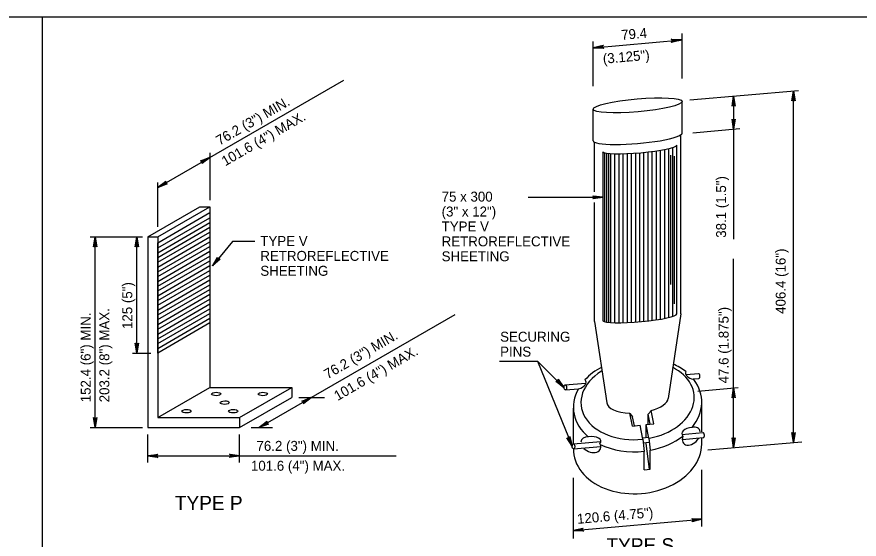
# Model space of a CAD drawing. Extents: x 640253 to 641999, y 298458 to 299646.
# Drawn here: x 640544.6 to 640798.8, y 298630.1 to 298787.7 of the extents above; entities that cross this region are included whole.
import ezdxf

# ---------------------------------------------------------------- set-up
doc = ezdxf.new("R2010")
doc.units = 0
doc.layers.add('1', color=7, linetype='Continuous')
doc.layers.add('2', color=7, linetype='Continuous')

msp = doc.modelspace()

# ---------------------------------------------------------------- linework, layer by layer
at = {"layer": '1'}
for p, q in [((640293.31, 298787.67), (641079.31, 298787.67)), ((640552.4, 298501.97), (640552.4, 298787.67))]:
    msp.add_line(p, q, dxfattribs=at)
at = {"layer": '2'}
for p, q in [((640745.35, 298769.11), (640745.35, 298782.64)), ((640718.51, 298778.37), (640745.35, 298780.72)), ((640718.51, 298766.76), (640718.51, 298780.28)), ((640587.19, 298736.22), (640643.29, 298768.61)), ((640747.71, 298762.61), (640780.48, 298765.48)), ((640760.93, 298763.77), (640760.93, 298753.8)), ((640778.98, 298659.27), (640778.98, 298765.33)), ((640745.35, 298752.61), (640745.35, 298762.15)), ((640718.51, 298750.3), (640718.51, 298759.84)), ((640748.58, 298752.71), (640762.8, 298753.96)), ((640760.93, 298753.8), (640760.93, 298720.65)), ((640744.97, 298698.11), (640744.96, 298752.08)), ((640718.9, 298734.89), (640718.9, 298749.84)), ((640742.61, 298697.33), (640742.61, 298748.3)), ((640743.76, 298748.51), (640743.55, 298748.73)), ((640743.77, 298698.07), (640743.76, 298748.98)), ((640602.93, 298732.38), (640602.93, 298746.61)), ((640721.41, 298746.98), (640721.41, 298696)), ((640721.41, 298746.59), (640721.63, 298746.81)), ((640722.06, 298695.59), (640722.06, 298746.56)), ((640722.61, 298695.59), (640722.61, 298746.55)), ((640723.24, 298695.59), (640723.24, 298746.56)), ((640723.86, 298695.45), (640723.86, 298746.43)), ((640725.11, 298695.4), (640725.11, 298746.37)), ((640726.36, 298695.39), (640726.36, 298746.36)), ((640727.61, 298695.4), (640727.61, 298746.38)), ((640728.86, 298695.45), (640728.86, 298746.42)), ((640730.11, 298695.51), (640730.11, 298746.48)), ((640731.36, 298695.59), (640731.36, 298746.57)), ((640732.61, 298695.69), (640732.61, 298746.66)), ((640733.86, 298695.81), (640733.86, 298746.78)), ((640735.11, 298695.94), (640735.11, 298746.91)), ((640736.36, 298696.1), (640736.36, 298747.07)), ((640737.61, 298696.27), (640737.61, 298747.24)), ((640738.86, 298696.47), (640738.86, 298747.44)), ((640740.11, 298696.7), (640740.11, 298747.67)), ((640741.36, 298696.98), (640741.36, 298747.95)), ((640741.93, 298706.99), (640741.93, 298745.92)), ((640743.12, 298701.13), (640743.12, 298745.69)), ((640587.19, 298724.38), (640587.19, 298737.68)), ((640698.95, 298733.24), (640721.41, 298733.24)), ((640584.12, 298721.28), (640599.86, 298730.37)), ((640587.12, 298721.28), (640602.86, 298730.37)), ((640599.86, 298730.37), (640602.86, 298730.37)), ((640602.86, 298730.37), (640602.86, 298675.87)), ((640718.91, 298695.83), (640718.9, 298731.67)), ((640587.12, 298717.99), (640602.86, 298727.08)), ((640587.12, 298716.54), (640602.86, 298725.63)), ((640587.12, 298715.1), (640602.86, 298724.19)), ((640587.12, 298713.66), (640602.86, 298722.75)), ((640566.74, 298721.28), (640582.49, 298721.28)), ((640568.28, 298663.78), (640568.28, 298721.28)), ((640580.82, 298686.28), (640580.82, 298721.28)), ((640584.12, 298721.28), (640587.12, 298721.28)), ((640584.12, 298721.28), (640584.12, 298663.78)), ((640587.12, 298712.21), (640602.86, 298721.3)), ((640587.12, 298721.28), (640587.12, 298666.78)), ((640587.12, 298710.77), (640602.86, 298719.86)), ((640587.12, 298719.28), (640587.35, 298719.68)), ((640587.12, 298719.32), (640587.32, 298719.66)), ((640587.12, 298709.33), (640602.86, 298718.41)), ((640609.71, 298719.96), (640603.7, 298712.54)), ((640616.48, 298719.96), (640609.71, 298719.96)), ((640587.12, 298707.88), (640602.86, 298716.97)), ((640587.12, 298706.44), (640602.86, 298715.53)), ((640587.12, 298705), (640602.86, 298714.09)), ((640587.12, 298703.55), (640602.86, 298712.64)), ((640760.93, 298657.71), (640760.93, 298714.7)), ((640587.12, 298702.11), (640602.86, 298711.2)), ((640587.12, 298700.67), (640602.86, 298709.75)), ((640587.12, 298699.22), (640602.86, 298708.31)), ((640587.12, 298697.78), (640602.86, 298706.87)), ((640587.12, 298696.34), (640602.86, 298705.43)), ((640587.12, 298694.89), (640602.86, 298703.98)), ((640587.12, 298693.45), (640602.86, 298702.54)), ((640587.12, 298692.01), (640602.86, 298701.09)), ((640587.12, 298690.56), (640602.86, 298699.65)), ((640587.12, 298689.12), (640602.86, 298698.21)), ((640617.72, 298663.78), (640676.89, 298697.94)), ((640744.97, 298698.11), (640741.18, 298672.58)), ((640587.12, 298687.68), (640602.86, 298696.76)), ((640718.91, 298695.83), (640722.69, 298671.24)), ((640579.47, 298686.28), (640585.04, 298686.28)), ((640690.3, 298683.85), (640701.76, 298683.85)), ((640701.76, 298683.85), (640709.73, 298675.91)), ((640701.76, 298683.85), (640712.18, 298658.13)), ((640746.61, 298679.77), (640750.3, 298680.09)), ((640710.07, 298676.65), (640716.25, 298677.17)), ((640748.75, 298678.44), (640750.42, 298678.58)), ((640587.12, 298666.78), (640602.86, 298675.87)), ((640602.86, 298675.87), (640627.58, 298675.87)), ((640611.84, 298666.78), (640627.58, 298675.87)), ((640627.58, 298675.87), (640627.58, 298672.87)), ((640710.18, 298675.14), (640714.07, 298675.47)), ((640750.09, 298674.81), (640762.33, 298675.88)), ((640611.84, 298663.78), (640627.58, 298672.87)), ((640629.69, 298672.87), (640637.47, 298672.87)), ((640712.57, 298658.9), (640712.57, 298669.6)), ((640751.32, 298662.52), (640751.32, 298671.49)), ((640587.12, 298666.78), (640611.84, 298666.78)), ((640611.84, 298666.78), (640611.84, 298663.78)), ((640730.36, 298664.26), (640729.56, 298668.13)), ((640729.58, 298668.02), (640730.45, 298667.02)), ((640731.01, 298664.3), (640730.45, 298667.02)), ((640736.01, 298668.88), (640735.1, 298667.79)), ((640735.1, 298664.75), (640735.1, 298667.79)), ((640735.72, 298664.82), (640735.1, 298667.79)), ((640736.83, 298664.91), (640736, 298668.9)), ((640730.36, 298664.26), (640732.68, 298664.47)), ((640733.56, 298660.25), (640732.68, 298664.47)), ((640734.51, 298664.7), (640736.83, 298664.91)), ((640735.37, 298660.56), (640734.51, 298664.7)), ((640734.51, 298660.92), (640734.51, 298664.7)), ((640566.74, 298663.78), (640582.49, 298663.78)), ((640584.12, 298663.78), (640611.84, 298663.78)), ((640584.12, 298653.23), (640584.12, 298661.74)), ((640611.84, 298653.23), (640611.84, 298661.74)), ((640615.31, 298663.78), (640621.72, 298663.78)), ((640745.28, 298661.72), (640751.64, 298662.26)), ((640712.51, 298658.91), (640720.85, 298659.63)), ((640733.46, 298660.71), (640735.31, 298660.86)), ((640733.56, 298660.25), (640733.88, 298656.62)), ((640733.65, 298659.21), (640735.48, 298659.36)), ((640735.5, 298651.22), (640734.51, 298659.03)), ((640735.37, 298660.56), (640735.7, 298656.93)), ((640745.44, 298660.21), (640751.77, 298660.75)), ((640751.32, 298658.55), (640751.32, 298660.75)), ((640753.15, 298657.03), (640781.49, 298659.51)), ((640712.63, 298657.41), (640720.84, 298658.11)), ((640733.88, 298651.05), (640733.88, 298656.62)), ((640735.7, 298651.21), (640735.7, 298656.93)), ((640584.12, 298655.27), (640659.11, 298655.27)), ((640733.88, 298651.05), (640735.7, 298651.21)), ((640751.32, 298633.93), (640751.32, 298651.02)), ((640712.57, 298630.28), (640712.57, 298648.65)), ((640712.57, 298632.73), (640751.32, 298636.12))]:
    msp.add_line(p, q, dxfattribs=at)
for points in [[(640721.62, 298778.25), (640721.48, 298778.47), (640718.51, 298778.37), (640721.62, 298778.25), (640721.78, 298778.13), (640718.51, 298778.37), (640721.45, 298778.78), (640721.54, 298779.01), (640718.51, 298778.37), (640721.69, 298779.17), (640721.54, 298779.01)], [(640721.62, 298778.25), (640721.48, 298778.47), (640718.51, 298778.37), (640721.62, 298778.25), (640721.78, 298778.13), (640718.51, 298778.37), (640721.45, 298778.78), (640721.54, 298779.01), (640718.51, 298778.37), (640721.69, 298779.17), (640721.54, 298779.01)], [(640742.24, 298780.84), (640742.38, 298780.63), (640745.35, 298780.72), (640742.24, 298780.84), (640742.07, 298780.96), (640745.35, 298780.72), (640742.41, 298780.32), (640742.32, 298780.09), (640745.35, 298780.72), (640742.17, 298779.92), (640742.32, 298780.09)], [(640760.57, 298760.91), (640760.78, 298761.02), (640760.93, 298763.77), (640760.57, 298760.91), (640760.45, 298760.77), (640760.93, 298763.77), (640761.06, 298761.02), (640761.27, 298760.92), (640760.93, 298763.77), (640761.41, 298760.77), (640761.27, 298760.92)], [(640778.62, 298762.47), (640778.83, 298762.58), (640778.98, 298765.33), (640778.62, 298762.47), (640778.5, 298762.33), (640778.98, 298765.33), (640779.12, 298762.58), (640779.32, 298762.48), (640778.98, 298765.33), (640779.46, 298762.33), (640779.32, 298762.48)], [(640761.29, 298756.65), (640761.08, 298756.54), (640760.93, 298753.8), (640761.29, 298756.65), (640761.41, 298756.8), (640760.93, 298753.8), (640760.79, 298756.54), (640760.59, 298756.64), (640760.93, 298753.8), (640760.45, 298756.8), (640760.59, 298756.64)], [(640600.28, 298744.19), (640600.48, 298744.07), (640602.93, 298745.31), (640600.28, 298744.19), (640600.09, 298744.23), (640602.93, 298745.31), (640600.62, 298743.82), (640600.64, 298743.59), (640602.93, 298745.31), (640600.57, 298743.39), (640600.64, 298743.59)], [(640589.84, 298737.33), (640589.64, 298737.46), (640587.19, 298736.22), (640589.84, 298737.33), (640590.03, 298737.3), (640587.19, 298736.22), (640589.5, 298737.71), (640589.48, 298737.93), (640587.19, 298736.22), (640589.55, 298738.13), (640589.48, 298737.93)], [(640718.56, 298733.6), (640718.66, 298733.39), (640721.41, 298733.24), (640718.56, 298733.6), (640718.41, 298733.72), (640721.41, 298733.24), (640718.66, 298733.11), (640718.56, 298732.9), (640721.41, 298733.24), (640718.41, 298732.76), (640718.56, 298732.9)], [(640567.92, 298718.43), (640568.13, 298718.53), (640568.28, 298721.28), (640567.92, 298718.43), (640567.8, 298718.28), (640568.28, 298721.28), (640568.42, 298718.53), (640568.62, 298718.43), (640568.28, 298721.28), (640568.76, 298718.28), (640568.62, 298718.43)], [(640580.46, 298718.43), (640580.67, 298718.53), (640580.82, 298721.28), (640580.46, 298718.43), (640580.34, 298718.28), (640580.82, 298721.28), (640580.96, 298718.53), (640581.16, 298718.43), (640580.82, 298721.28), (640581.3, 298718.28), (640581.16, 298718.43)], [(640605.78, 298714.53), (640605.55, 298714.58), (640603.7, 298712.54), (640605.78, 298714.53), (640605.97, 298714.56), (640603.7, 298712.54), (640605.33, 298714.75), (640605.23, 298714.96), (640603.7, 298712.54), (640605.22, 298715.17), (640605.23, 298714.96)], [(640581.18, 298689.13), (640580.97, 298689.03), (640580.82, 298686.28), (640581.18, 298689.13), (640581.3, 298689.28), (640580.82, 298686.28), (640580.69, 298689.03), (640580.48, 298689.13), (640580.82, 298686.28), (640580.34, 298689.28), (640580.48, 298689.13)], [(640707.95, 298678.17), (640707.88, 298677.95), (640709.73, 298675.91), (640707.95, 298678.17), (640707.93, 298678.36), (640709.73, 298675.91), (640707.68, 298677.74), (640707.47, 298677.67), (640709.73, 298675.91), (640707.26, 298677.68), (640707.47, 298677.67)], [(640760.57, 298672.9), (640760.78, 298673.01), (640760.93, 298675.75), (640760.57, 298672.9), (640760.45, 298672.75), (640760.93, 298675.75), (640761.06, 298673.01), (640761.27, 298672.91), (640760.93, 298675.75), (640761.41, 298672.75), (640761.27, 298672.91)], [(640630.82, 298671.76), (640631.02, 298671.63), (640633.47, 298672.87), (640630.82, 298671.76), (640630.63, 298671.79), (640633.47, 298672.87), (640631.16, 298671.38), (640631.18, 298671.16), (640633.47, 298672.87), (640631.11, 298670.96), (640631.18, 298671.16)], [(640568.64, 298666.63), (640568.43, 298666.53), (640568.28, 298663.78), (640568.64, 298666.63), (640568.76, 298666.78), (640568.28, 298663.78), (640568.14, 298666.53), (640567.94, 298666.63), (640568.28, 298663.78), (640567.8, 298666.78), (640567.94, 298666.63)], [(640620.37, 298664.9), (640620.18, 298665.02), (640617.72, 298663.78), (640620.37, 298664.9), (640620.56, 298664.86), (640617.72, 298663.78), (640620.03, 298665.27), (640620.02, 298665.5), (640617.72, 298663.78), (640620.08, 298665.69), (640620.02, 298665.5)], [(640779.34, 298662.13), (640779.13, 298662.02), (640778.98, 298659.27), (640779.34, 298662.13), (640779.46, 298662.27), (640778.98, 298659.27), (640778.85, 298662.02), (640778.64, 298662.12), (640778.98, 298659.27), (640778.5, 298662.27), (640778.64, 298662.12)], [(640711.42, 298660.91), (640711.27, 298660.73), (640712.18, 298658.13), (640711.42, 298660.91), (640711.48, 298661.09), (640712.18, 298658.13), (640711.01, 298660.62), (640710.78, 298660.64), (640712.18, 298658.13), (640710.59, 298660.73), (640710.78, 298660.64)], [(640761.29, 298660.57), (640761.08, 298660.46), (640760.93, 298657.71), (640761.29, 298660.57), (640761.41, 298660.71), (640760.93, 298657.71), (640760.79, 298660.46), (640760.59, 298660.56), (640760.93, 298657.71), (640760.45, 298660.71), (640760.59, 298660.56)], [(640586.97, 298654.91), (640586.87, 298655.12), (640584.12, 298655.27), (640586.97, 298654.91), (640587.12, 298654.79), (640584.12, 298655.27), (640586.87, 298655.41), (640586.97, 298655.61), (640584.12, 298655.27), (640587.12, 298655.75), (640586.97, 298655.61)], [(640608.98, 298655.63), (640609.09, 298655.42), (640611.84, 298655.27), (640608.98, 298655.63), (640608.84, 298655.75), (640611.84, 298655.27), (640609.09, 298655.14), (640608.99, 298654.93), (640611.84, 298655.27), (640608.84, 298654.79), (640608.99, 298654.93)], [(640748.44, 298636.23), (640748.57, 298636.03), (640751.32, 298636.12), (640748.44, 298636.23), (640748.29, 298636.34), (640751.32, 298636.12), (640748.6, 298635.75), (640748.51, 298635.53), (640751.32, 298636.12), (640748.37, 298635.38), (640748.51, 298635.53)], [(640715.45, 298632.62), (640715.32, 298632.82), (640712.57, 298632.73), (640715.45, 298632.62), (640715.6, 298632.51), (640712.57, 298632.73), (640715.29, 298633.1), (640715.37, 298633.32), (640712.57, 298632.73), (640715.52, 298633.47), (640715.37, 298633.32)]]:
    msp.add_lwpolyline(points, dxfattribs=at)
msp.add_lwpolyline([(640587.12, 298686.28), (640587.12, 298719.55), (640602.86, 298728.64), (640602.86, 298695.37)], close=True, dxfattribs=at)
for centre, major_axis, ratio in [((640731.93, 298760.98), (13.42, 1.17), 0.145281), ((640604.79, 298673.91), (1.39, 0.03), 0.379302), ((640618.87, 298673.91), (1.39, 0.03), 0.379302), ((640710.12, 298675.89), (0.064, -0.752), 0.512732), ((640607.35, 298671.32), (1.39, 0.03), 0.379302), ((640595.82, 298668.73), (1.39, 0.03), 0.379302), ((640609.91, 298668.73), (1.39, 0.03), 0.379302), ((640712.57, 298658.16), (0.064, -0.752), 0.512732)]:
    msp.add_ellipse(centre, major_axis=major_axis, ratio=ratio, dxfattribs=at)
for centre, major_axis, ratio, start_param, end_param in [((640731.93, 298751.43), (13.42, 1.17), 0.145281, 3.11632, 6.285895), ((640732.57, 298748.05), (11.2, 0.98), 0.122972, 3.210002, 6.25293), ((640732.58, 298697.08), (11.2, 0.98), 0.122972, 3.210002, 6.291685), ((640731.94, 298670.7), (19.33, 1.69), 0.73071, 2.097917, 2.468804), ((640731.94, 298672.08), (17.07, 1.49), 0.694967, 4.864246, 7.131508), ((640731.94, 298670.7), (19.33, 1.69), 0.73071, 0.656059, 0.918196), ((640731.94, 298672.08), (17.07, 1.49), 0.694967, 2.202733, 4.738504), ((640750.78, 298680.04), (4.38, -0.28), 0.475219, 2.977963, 4.296796), ((640750.36, 298679.33), (0.064, -0.752), 0.512732, 0.00107, 3.141593), ((640712.01, 298677.2), (-4.38, -0.28), 0.475219, 2.036448, 3.493745), ((640731.94, 298670.7), (19.33, 1.69), 0.73071, 5.661526, 6.723992), ((640731.94, 298670.7), (19.33, 1.69), 0.73071, 2.680187, 3.772289), ((640732.14, 298672.12), (9.04, 0.79), 0.424128, 5.116194, 6.19738), ((640731.73, 298672.03), (9.04, 0.79), 0.424128, 3.141593, 4.432781), ((640748.15, 298661.2), (2.24, 2.27), 0.672987, 5.779184, 7.175378), ((640748.9, 298662.15), (3.65, 0.24), 0.475219, 1.675831, 3.574843), ((640751.7, 298661.51), (0.064, -0.752), 0.512732, 0.00107, 3.141593), ((640717.83, 298658.61), (2.87, -1.38), 0.672987, 2.130551, 3.418187), ((640717.22, 298659.25), (-3.62, -0.53), 0.475219, 2.692089, 4.679207), ((640731.94, 298670.7), (19.33, 1.69), 0.73071, 4.853626, 5.433989), ((640748.15, 298661.2), (2.24, 2.27), 0.672987, 2.176573, 5.044432), ((640731.94, 298658.04), (19.33, 1.69), 0.73071, 3.065603, 6.219513), ((640717.83, 298658.61), (2.87, -1.38), 0.672987, 4.245803, 7.059428), ((640731.94, 298670.7), (19.33, 1.69), 0.73071, 4.023734, 4.749104)]:
    msp.add_ellipse(centre, major_axis=major_axis, ratio=ratio, start_param=start_param, end_param=end_param, dxfattribs=at)

# ---------------------------------------------------------------- texts
for s, rotation, p in [('79.4', 5.0068, (640727.12, 298780.7)), ('(3.125")', 5.0068, (640721.59, 298773.52)), ('76.2 (3") MIN.', 30, (640605.81, 298748.79)), ('101.6 (4") MAX.', 30, (640607.5, 298742.55)), ('38.1 (1.5")', 90, (640758.64, 298721.04)), ('406.4 (16")', 90, (640776.61, 298698.08)), ('125 (5")', 90, (640579.45, 298693.52)), ('47.6 (1.875")', 90, (640759.4, 298677.12)), ('152.4 (6") MIN.', 90, (640566.91, 298671.41)), ('203.2 (8") MAX.', 90, (640572.53, 298671.41)), ('76.2 (3") MIN.', 30, (640638.4, 298678.32)), ('101.6 (4") MAX.', 30, (640641.43, 298671.78)), ('120.6 (4.75")', 5.0052, (640713.8, 298634.73))]:
    msp.add_text(s, height=3, rotation=rotation, dxfattribs=at).set_placement(p)
for s, height, p in [('75 x 300', 3, (640672.81, 298731.95)), ('(3" x 12")', 3, (640672.81, 298727.45)), ('TYPE V', 3, (640672.81, 298722.95)), ('TYPE V', 3, (640618.1, 298718.57)), ('RETROREFLECTIVE', 3, (640672.81, 298718.45)), ('RETROREFLECTIVE', 3, (640618.1, 298714.07)), ('SHEETING', 3, (640672.81, 298713.95)), ('SHEETING', 3, (640618.1, 298709.57)), ('SECURING', 3, (640690.46, 298689.69)), ('PINS', 3, (640690.46, 298685.19)), ('76.2 (3") MIN.', 3, (640616.93, 298656.77)), ('101.6 (4") MAX.', 3, (640615.26, 298650.77)), ('TYPE P', 4.3, (640592.3, 298638.89)), ('TYPE S', 4.3, (640722.54, 298626.11))]:
    msp.add_text(s, height=height, dxfattribs=at).set_placement(p)

doc.saveas('drawing.dxf')
